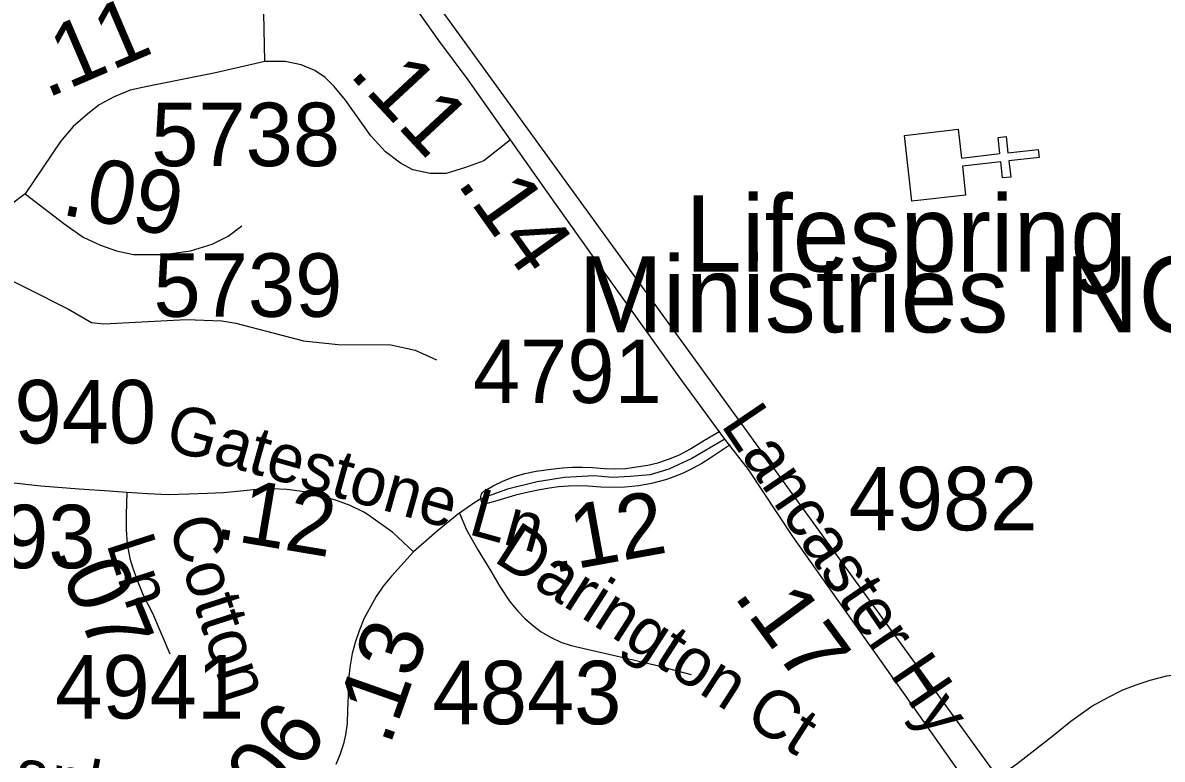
# Model space of a CAD drawing. Extents: x 1383679 to 1536984, y 460658 to 651027.
# Drawn here: x 1438104 to 1440347, y 479854 to 481304 of the extents above; entities that cross this region are included whole.
import ezdxf

# ---------------------------------------------------------------- set-up
doc = ezdxf.new("R2010")
doc.units = 0
for name, color, linetype in [('Default', 7, 'Continuous'), ('Exist Boundary Political City Limit New', 7, 'Continuous'), ('Exist Cultural Church CELL', 7, 'Continuous'), ('Exist Cultural Church Label', 7, 'Continuous'), ('Exist Hydrographic Misc Water Feature', 7, 'Continuous'), ('Exist Road Non-System Type 51', 7, 'Continuous'), ('Exist Road Secondary Mileage Hundredths English Label', 7, 'Continuous'), ('Exist Road Secondary Type 51 Attributed', 7, 'Continuous'), ('Exist Road Secondary Type 51 Label', 7, 'Continuous'), ('Exist Road Secondary Type 51 Number Label', 7, 'Continuous'), ('Map Preparation Boundary City Limit Buffer Line', 7, 'Continuous')]:
    doc.layers.add(name, color=color, linetype=linetype)

msp = doc.modelspace()

# ---------------------------------------------------------------- linework, layer by layer
at = {"layer": 'Default'}
msp.add_lwpolyline([(1441312.6, 477738.3), (1440841.1, 478613.6), (1440494.9, 479168.9), (1438643.9, 481722.4), (1438571.1, 481863), (1438528.9, 482013), (1439066.9, 482218.1), (1438964.6, 482336), (1438946.5, 482410.8), (1438821.4, 482633.1), (1438711.2, 482746.7), (1438617.9, 482971.1), (1438423.8, 483045.8), (1438419.2, 483089.7), (1438418.1, 483095.9)], dxfattribs=at)
at = {"layer": 'Exist Boundary Political City Limit New'}
msp.add_lwpolyline([(1441312.6, 477738.3), (1440841.1, 478613.6), (1440494.9, 479168.9), (1438643.9, 481722.4), (1438571.1, 481863), (1438528.9, 482013), (1439066.9, 482218.1), (1438964.6, 482336), (1438946.5, 482410.8), (1438821.4, 482633.1), (1438711.2, 482746.7), (1438617.9, 482971.1), (1438423.8, 483045.8), (1438419.2, 483089.7), (1438418.1, 483095.9)], dxfattribs=at)
at = {"layer": 'Exist Cultural Church CELL'}
msp.add_lwpolyline([(1439945.6, 481094.7), (1439952.1, 481038.1), (1440027.8, 481046.7), (1440024.2, 481078.5), (1440040.1, 481080.2), (1440043.7, 481048.4), (1440103.4, 481055.2), (1440105.2, 481039.3), (1440045.5, 481032.5), (1440049.1, 481000.7), (1440033.2, 480998.9), (1440029.6, 481030.7), (1439953.9, 481022.2), (1439960.3, 480964.9), (1439854.5, 480952.9), (1439839.9, 481082.7)], close=True, dxfattribs=at)
at = {"layer": 'Exist Hydrographic Misc Water Feature'}
msp.add_lwpolyline([(1438031.5, 480821.9), (1438193.9, 480740.7), (1438239.5, 480714.3), (1438263.4, 480711.3), (1438425.7, 480720.4), (1438495.6, 480717.3), (1438523.6, 480712.7), (1438656.9, 480678), (1438724.8, 480670.9), (1438828.9, 480670.4), (1438876.7, 480659.6), (1438918.3, 480640.8)], dxfattribs=at)
at = {"layer": 'Exist Road Non-System Type 51'}
for points in [[(1439496.6, 480473.2), (1439457.4, 480446.9), (1439441.1, 480436.4), (1439422.7, 480426.5), (1439405.3, 480418.5), (1439387.9, 480411.2), (1439369.7, 480404.4), (1439342, 480397.3), (1439316.7, 480392.6), (1439289.5, 480389.8), (1439267.4, 480389.2), (1439242, 480390), (1439217, 480392), (1439195.3, 480392.8), (1439178.4, 480392), (1439158.8, 480390.4), (1439140.8, 480388.3), (1439122.2, 480384.7), (1439099.8, 480380.4), (1439074.1, 480373.9), (1439037.5, 480363.2), (1439012.8, 480356.6), (1439011.5, 480356.7), (1439010.2, 480357.4), (1439008.7, 480358.9), (1439006.8, 480362.4), (1439006.1, 480366.7), (1439006.1, 480367.1), (1439005.9, 480371.8), (1439006.7, 480374.5), (1439007.4, 480376.3), (1439009.2, 480379.6), (1439011.7, 480381.9), (1439017.8, 480385.6), (1439030.2, 480392.6), (1439050.3, 480402.7), (1439072.2, 480411.3), (1439092.6, 480417.2), (1439114.6, 480421.3), (1439143.8, 480425.6), (1439166.3, 480428), (1439186.1, 480429.3), (1439205, 480429.5), (1439225.8, 480428.6), (1439248.5, 480426.7), (1439270.6, 480426), (1439291, 480426.7), (1439312, 480429.7), (1439334.9, 480433.5), (1439354.6, 480438.1), (1439375.5, 480444.9), (1439396.7, 480453.7), (1439417.5, 480464.9), (1439446.2, 480482.3), (1439476.1, 480500.4)], [(1439977.4, 479786.9), (1440017.6, 479814.8), (1440061.2, 479844.9), (1440129.2, 479898.2), (1440167.8, 479929.2), (1440209.1, 479958.8), (1440241.9, 479976.7), (1440270.1, 479990.8), (1440295.9, 480000.8), (1440323.4, 480009.9), (1440356.6, 480018.2), (1440385.6, 480022.3), (1440400.6, 480024.8)]]:
    msp.add_lwpolyline(points, dxfattribs=at)
at = {"layer": 'Exist Road Secondary Type 51 Attributed'}
for points in [[(1439064, 481073.9), (1439044.9, 481101), (1438981, 481192.4), (1438923.3, 481269.8), (1438790.5, 481457.1), (1438726.9, 481549.7), (1438685.1, 481608.9), (1438657.2, 481648.6), (1438627.7, 481691.5), (1438606.7, 481726.6), (1438585.4, 481765.8), (1438565.3, 481806.3), (1438545.5, 481851.7), (1438525.6, 481908.3), (1438511.8, 481952.3), (1438501.4, 481994.8), (1438492.7, 482036), (1438484.7, 482092.6)], [(1438580.2, 481228.2), (1438578.2, 481323.5), (1438575, 481358.6), (1438565.5, 481396.9), (1438526.3, 481457.5), (1438492.6, 481509.2), (1438470.1, 481542.9), (1438445.4, 481565.4), (1438440.2, 481574.6), (1438427.9, 481590)], [(1438580.2, 481228.2), (1438483.6, 481205.7), (1438348.8, 481178.8), (1438315.1, 481172), (1438283.7, 481158.5), (1438254.5, 481142.8), (1438232, 481124.8), (1438202.8, 481100.1), (1438178.1, 481070.9), (1438108.5, 480967.5)], [(1439064, 481073.9), (1439011.4, 481032.7), (1438975.5, 481019.2), (1438937.3, 481007.9), (1438905.8, 481007.9), (1438872.2, 481014.7), (1438847.4, 481028.2), (1438818.2, 481050.6), (1438789, 481082.1), (1438739.6, 481151.8), (1438717.2, 481178.8), (1438699.2, 481196.7), (1438679, 481210.2), (1438652, 481221.5), (1438620.6, 481228.2), (1438580.2, 481228.2)], [(1439486.3, 480484.8), (1439396, 480607.1), (1439259.4, 480799), (1439152.2, 480949.2), (1439064, 481073.9)], [(1438108.5, 480967.5), (1438079.3, 480945), (1438054.6, 480922.5), (1438025.4, 480909), (1437985, 480895.5)], [(1438108.5, 480967.5), (1438184.9, 480909), (1438223, 480882.1), (1438256.7, 480866.3), (1438288.2, 480855.1), (1438321.9, 480848.3), (1438382.5, 480848.3), (1438434.2, 480855.1), (1438476.8, 480868.6), (1438508.3, 480884.3), (1438535.2, 480904.5)], [(1438308.6, 480379.6), (1438274.8, 480382.1), (1438214.9, 480386.2), (1438139.6, 480392), (1438075, 480399.3), (1438069.3, 480399.9), (1438027.5, 480403.8), (1437963.5, 480413.2), (1437875.4, 480426.9), (1437775.3, 480443.1), (1437714, 480452.8), (1437668.6, 480460.1), (1437621.3, 480466.8), (1437552.1, 480478.2)], [(1439486.3, 480484.8), (1439421, 480446.1), (1439376.2, 480425.4), (1439339.4, 480414.4), (1439299.6, 480410.9), (1439265.1, 480409.1), (1439228.8, 480412.6), (1439170.8, 480409.1), (1439116.4, 480400.3), (1439058.4, 480386.2), (1439006.1, 480366.7), (1438993.9, 480359.8), (1438963.6, 480338.7)], [(1439978, 479786.1), (1439958.7, 479813.6), (1439838.8, 479984.5), (1439619.8, 480293.1), (1439532.9, 480424.8), (1439486.3, 480484.8)], [(1438873.2, 480262.7), (1438832.3, 480300.8), (1438784.3, 480335.1), (1438775.4, 480340.5), (1438748.5, 480353.8), (1438721.5, 480363.8), (1438690.6, 480373.1), (1438658.7, 480380.8), (1438623.9, 480385.5), (1438594.1, 480386.6), (1438564.9, 480385.3), (1438532.3, 480382.1), (1438499.3, 480378.7), (1438467.6, 480377.2), (1438431.1, 480375.9), (1438390.4, 480375), (1438349.2, 480376.7), (1438308.6, 480379.6)], [(1438308.6, 480379.6), (1438307.4, 480336.4), (1438307.4, 480306.3), (1438309.6, 480278), (1438314.7, 480249.7), (1438320.4, 480230.5), (1438328.8, 480206.6), (1438340.8, 480177), (1438359.1, 480141.7), (1438393.5, 480061.5)], [(1438963.6, 480338.7), (1438959.2, 480335.7), (1438919.7, 480303.6), (1438873.2, 480262.7)], [(1438963.6, 480338.7), (1438977.6, 480305.9), (1438999.9, 480266.5), (1439024.8, 480226.2), (1439043.5, 480194.6), (1439062.4, 480165.4), (1439078.8, 480145.5), (1439092.7, 480131.1), (1439109.9, 480116.4), (1439124.8, 480105.1), (1439144.1, 480093.9), (1439163.4, 480084.9), (1439183.4, 480078.4), (1439217.8, 480070.2), (1439275, 480057.5), (1439347.9, 480040.4), (1439420.1, 480021.1)], [(1438873.2, 480262.7), (1438829.8, 480214.6), (1438813.5, 480194.9), (1438800, 480174.9), (1438789.2, 480155.6), (1438776.4, 480131.9), (1438766.2, 480107.4), (1438758.9, 480086.4), (1438752.3, 480062.7), (1438747.8, 480034.6), (1438745, 480010), (1438744.3, 479980), (1438743, 479950.7), (1438742.4, 479924.7), (1438739.6, 479902.6), (1438735.3, 479884.3), (1438728.4, 479863), (1438720.2, 479843.9)]]:
    msp.add_lwpolyline(points, dxfattribs=at)
at = {"layer": 'Map Preparation Boundary City Limit Buffer Line'}
msp.add_lwpolyline([(1441312.6, 477738.3), (1440841.1, 478613.6), (1440494.9, 479168.9), (1438643.9, 481722.4), (1438571.1, 481863), (1438528.9, 482013), (1439066.9, 482218.1), (1438964.6, 482336), (1438946.5, 482410.8), (1438821.4, 482633.1), (1438711.2, 482746.7), (1438617.9, 482971.1), (1438423.8, 483045.8), (1438419.2, 483089.7), (1438418.1, 483095.9)], dxfattribs=at)
msp.add_lwpolyline([(1441312.6, 477738.3), (1440841.1, 478613.6), (1440494.9, 479168.9), (1438643.9, 481722.4), (1438571.1, 481863), (1438528.9, 482013), (1439066.9, 482218.1), (1438964.6, 482336), (1438946.5, 482410.8), (1438821.4, 482633.1), (1438711.2, 482746.7), (1438617.9, 482971.1), (1438423.8, 483045.8), (1438419.2, 483089.7), (1438418.1, 483095.9)], dxfattribs=at)

# ---------------------------------------------------------------- texts
at = {"layer": 'Exist Cultural Church Label'}
for s, p in [('Lifespring', (1439408.1, 480814.5)), ('Ministries INC.', (1439197.4, 480694.7))]:
    msp.add_text(s, height=150, rotation=0, dxfattribs=at).set_placement(p)
at = {"layer": 'Exist Road Secondary Mileage Hundredths English Label'}
for s, rotation, p in [('.11', 23.2143, (1438150.8, 481155.1)), ('.11', 312.8576, (1438744.1, 481202.9)), ('.09', 348.6823, (1438176.8, 480927.6)), ('.14', 305.4477, (1438957.1, 480988.8)), ('.12', 350.4164, (1438478.6, 480290.6)), ('.12', 10.2569, (1439147.8, 480220.6)), ('.07', 292.214, (1438162.1, 480263.2)), ('.17', 306.3594, (1439501.8, 480176.5)), ('.13', 70.6126, (1438826.3, 479878.6)), ('.06', 52.7291, (1438566.4, 479718.4))]:
    msp.add_text(s, height=125, rotation=rotation, dxfattribs=at).set_placement(p)
at = {"layer": 'Exist Road Secondary Type 51 Label'}
for s, rotation, p in [('Gatestone Ln', 344.3235, (1438380.1, 480466.1)), ('Lancaster Hy', 304.1217, (1439477, 480512.3)), ('Cotton', 287.8849, (1438389.6, 480318.2)), ('Darington Ct', 327.2677, (1439028.5, 480245.3)), ('Ln', 287.8849, (1438267.9, 480279)), ('Danby Rd', 349.2238, (1437989.5, 479802.8))]:
    msp.add_text(s, height=95, rotation=rotation, dxfattribs=at).set_placement(p)
at = {"layer": 'Exist Road Secondary Type 51 Number Label'}
for s, p in [('5738', (1438356.7, 481022.1)), ('5739', (1438361.2, 480725.4)), ('4791', (1438990.2, 480555.7)), ('4940', (1437994.5, 480476.1)), ('4982', (1439729.9, 480305)), ('4793', (1437875.3, 480230.3)), ('4941', (1438167.7, 479934.3)), ('4843', (1438910.7, 479923.1))]:
    msp.add_text(s, height=125, dxfattribs=at).set_placement(p)

doc.saveas('drawing.dxf')
